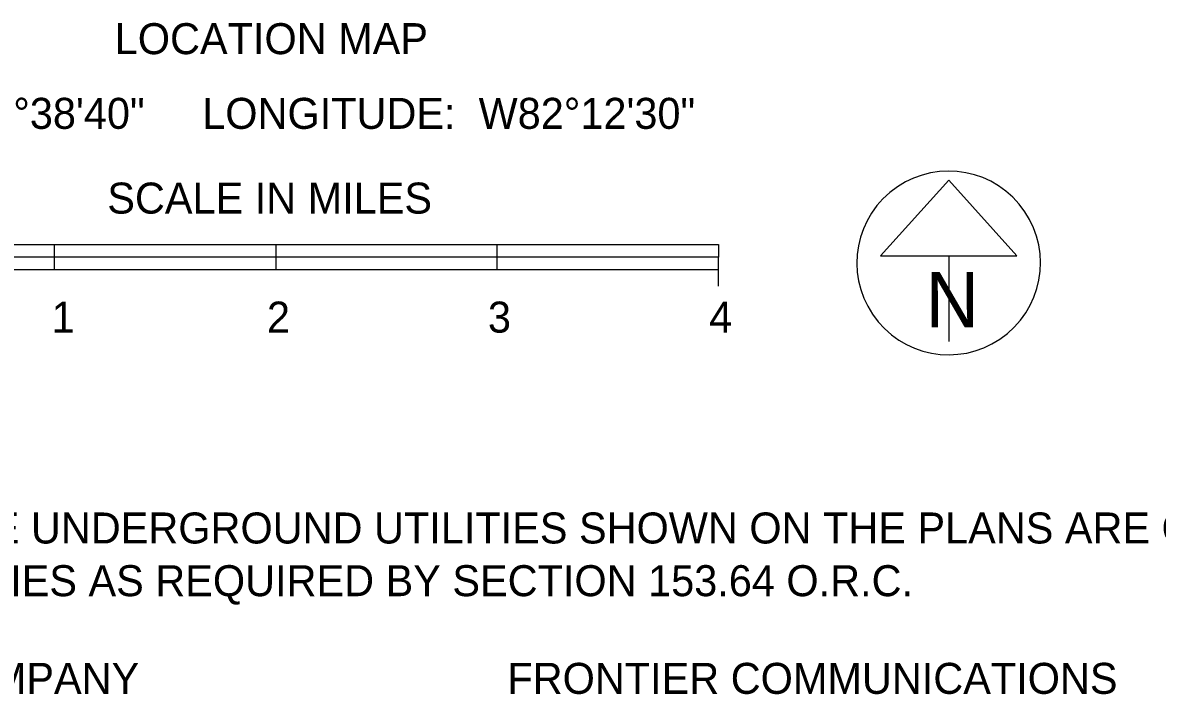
# Model space of a CAD drawing. Extents: x 0 to 34, y 0 to 22.
# Drawn here: x 4.12 to 9.24, y 11.12 to 14.15 of the extents above; entities that cross this region are included whole.
import ezdxf

# ---------------------------------------------------------------- set-up
doc = ezdxf.new("R2010")
doc.units = 0
doc.layers.add('SH_Data', color=7, linetype='Continuous')
doc.layers.add('SH_Text', color=7, linetype='Continuous')

msp = doc.modelspace()

# ---------------------------------------------------------------- linework, layer by layer
at = {"layer": 'SH_Data'}
for p, q in [((8.2995, 13.4375), (7.9919, 13.0962)), ((8.6071, 13.0962), (8.2995, 13.4375)), ((4.0102, 13.1466), (4.2602, 13.1466)), ((4.2602, 13.0904), (4.2602, 13.1466)), ((4.2602, 13.1466), (5.2602, 13.1466)), ((5.2602, 13.1466), (5.2602, 13.0904)), ((5.2602, 13.1466), (6.2602, 13.1466)), ((6.2602, 13.0904), (6.2602, 13.1466)), ((6.2602, 13.1466), (7.2602, 13.1466)), ((7.2602, 13.1466), (7.2602, 13.0904)), ((4.2602, 13.0904), (4.0102, 13.0904)), ((4.2602, 13.0341), (4.2602, 13.0904)), ((5.2602, 13.0904), (4.2602, 13.0904)), ((6.2602, 13.0904), (5.2602, 13.0904)), ((5.2602, 13.0904), (5.2602, 13.0341)), ((6.2602, 13.0341), (6.2602, 13.0904)), ((7.2602, 13.0904), (6.2602, 13.0904)), ((7.2602, 12.9591), (7.2602, 13.0904)), ((7.9919, 13.0962), (8.6071, 13.0962)), ((8.2995, 13.0962), (8.2995, 12.7095)), ((4.0102, 13.0341), (4.2602, 13.0341)), ((4.2602, 13.0341), (5.2602, 13.0341)), ((5.2602, 13.0341), (6.2602, 13.0341)), ((6.2602, 13.0341), (7.2602, 13.0341))]:
    msp.add_line(p, q, dxfattribs=at)
msp.add_arc((8.2995, 13.0637), 0.4148, 129.7798, 129.7633, dxfattribs=at)

# ---------------------------------------------------------------- texts
for s, height, p in [('LATITUDE:  N40°38\'40"     LONGITUDE:  W82°12\'30"', 0.14, (2.6698, 13.6693)), ('N', 0.25, (8.1954, 12.7724))]:
    msp.add_text(s, height=height, dxfattribs=at).set_placement(p)
at = {"layer": 'SH_Text'}
for s, p in [('LOCATION MAP', (4.5327, 14.0066)), ('SCALE IN MILES', (4.499, 13.2866)), ('1', (4.2473, 12.7491)), ('2', (5.2202, 12.7491)), ('3', (6.2183, 12.7491)), ('4', (7.2175, 12.7491)), ('THE LOCATION OF THE UNDERGROUND UTILITIES SHOWN ON THE PLANS ARE OBTAINED FROM THE', (1.9802, 11.7967)), ('OWNER OF THE UTILITIES AS REQUIRED BY SECTION 153.64 O.R.C.', (1.9802, 11.5587)), ('AEP OHIO POWER COMPANY', (1.9802, 11.1176)), ('FRONTIER COMMUNICATIONS', (6.3062, 11.1176))]:
    msp.add_text(s, height=0.14, dxfattribs=at).set_placement(p)

doc.saveas('drawing.dxf')
